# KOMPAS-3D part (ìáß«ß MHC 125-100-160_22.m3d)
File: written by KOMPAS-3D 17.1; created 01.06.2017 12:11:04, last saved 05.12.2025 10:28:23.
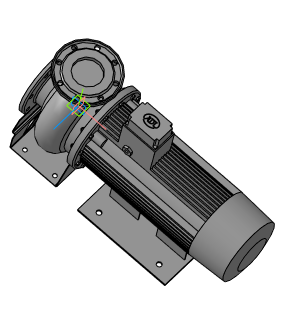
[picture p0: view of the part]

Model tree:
1. Операция без истории:3

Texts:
  ООО АДЛ ГРУПП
